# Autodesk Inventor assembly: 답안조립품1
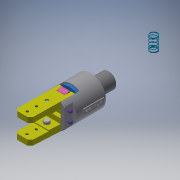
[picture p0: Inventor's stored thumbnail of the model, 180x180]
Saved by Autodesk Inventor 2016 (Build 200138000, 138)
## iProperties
Created: 2019-02
Part Number: 답안조립품1
Material: 일반
Document SubType Name: Assembly
Designer: 605-11
Author: 605-11
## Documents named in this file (10)
- C:\Users\605-11\Desktop\490207V1015\답안조립품1.iam
- C:\Users\605-11\Desktop\490207V1015\본체.ipt
- C:\Users\605-11\Desktop\490207V1015\피스톤.ipt
- C:\Users\605-11\Desktop\490207V1015\O-링.ipt
- C:\Users\605-11\Desktop\490207V1015\가이드핀.ipt
- C:\Users\605-11\Desktop\490207V1015\부시.ipt
- C:\Users\605-11\Desktop\490207V1015\평행핀 6x28.ipt
- C:\Users\605-11\Desktop\490207V1015\핀.ipt
- C:\Users\605-11\Desktop\490207V1015\핑거.ipt
- C:\Users\605-11\Desktop\490207V1015\스프링.ipt
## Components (9 placed, 5 different names)
1. 피스톤:1
2. O-링:1
3. O-링:2
4. 가이드핀:1
5. 핀:1
6. 핑거:1 — 플러쉬:1
7. 핀:4
8. 핑거:3
9. 가이드핀:2
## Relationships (1: Flush 1)
- 플러쉬:1 [Flush]: 핑거:1
## Named parameters: d18_d8 = 0, d19_d15 = 0, d20_d4 = 0, d21_d6 = 0
